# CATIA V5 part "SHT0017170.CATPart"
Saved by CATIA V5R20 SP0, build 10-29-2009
Part number: Part266
Bounding box of the stored display mesh (mm): x 0 to 89.712, y -993.394 to 0, z 0 to 1255.88
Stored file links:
  D:\新建文件夹\宋国明\项目\02-福田A6-张甲\骨架钣金\2D\SHT0017170-主驾靠背上弯管\SHT0017170.CATPart
  kaobeigujia--_AllCATPart.CATPart

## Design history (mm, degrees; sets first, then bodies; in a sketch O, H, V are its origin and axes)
AxisSystem1: origin (0, 0, 0), X (1, 0, 0), Y (0, 1, 0), Z (0, 0, 1)
Set1
  Point1: type Center, Curve edge [face of Solid1 | face of Solid1]
  Point2: type Center, Curve edge [face of Solid1 | face of Solid1]
  Line1: type PtPt, FirstPoint Point2, SecondPoint Point1
  Point3: type Center, Curve edge [face of Solid1 | face of Solid1]
  Point4: type Center, Curve edge [face of Solid1 | face of Solid1]
  Line2: type PtPt, FirstPoint Point3, SecondPoint Point4
  Point5: type OnCurve, Support Line2, Ratio 0.5
  Point6: type OnCurve, Support Line1, Ratio 0.5
  Line3: type PtPt, FirstPoint Point5, SecondPoint Point6
  Plane1: type 2Lines, Element1 Line3, Element2 Line1
  MultiExtract1: ListOfMultiExtractConstraints MultiExtractConstraint edge [face of Solid1 | face of Solid1]
  Point7: type Center, Curve MultiExtract1
Body1 (main body)
Body2
  Solid1: solid without history
Body3 "几何体.81"
  Solid2: solid without history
